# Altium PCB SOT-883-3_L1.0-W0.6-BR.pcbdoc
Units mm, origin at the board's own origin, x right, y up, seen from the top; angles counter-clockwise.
Board outline 14.3 x 13.7 mm, 2 copper layers (Top Layer, Bottom Layer), stack 0.07 mm thick; 1 components, 0 nets, 3 pads, 0 vias.
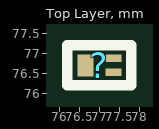
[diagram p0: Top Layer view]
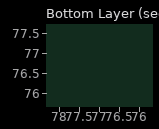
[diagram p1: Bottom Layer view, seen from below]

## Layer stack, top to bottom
Top Solder Mask Layer: solder mask 0.01, Dk 3.3
Top Layer: signal copper 0.035
Bottom Layer: signal copper 0.035
Bottom Solder Mask Layer: solder mask 0.01, Dk 3.3

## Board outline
84.15,69.85 69.85,69.85 69.85,83.55 84.15,83.55

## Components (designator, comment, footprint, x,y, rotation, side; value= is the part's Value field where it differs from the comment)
? "SOT-883-3_L1.0-W0.6-BR" SOT-883-3_L1.0-W0.6-BR 77,76.7 r0 top

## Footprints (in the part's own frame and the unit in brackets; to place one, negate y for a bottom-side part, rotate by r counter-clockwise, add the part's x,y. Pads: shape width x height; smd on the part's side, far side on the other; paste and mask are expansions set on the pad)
SOT-883-3_L1.0-W0.6-BR [mm]
  rect 0.4x0.18 smd paste+0 mask+0.05: 1(0.35,-0.175) 2(0.35,0.175)
  rect 0.4x0.55 smd paste+0 mask+0.05: 3(-0.35,0)
  silkscreen extent -0.8,-0.5 0.8,0.5

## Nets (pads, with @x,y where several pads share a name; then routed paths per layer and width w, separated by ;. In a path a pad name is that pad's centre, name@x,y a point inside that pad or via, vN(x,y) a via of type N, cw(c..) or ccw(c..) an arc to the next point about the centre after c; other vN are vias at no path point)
pads on no net: ?.1 ?.2 ?.3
